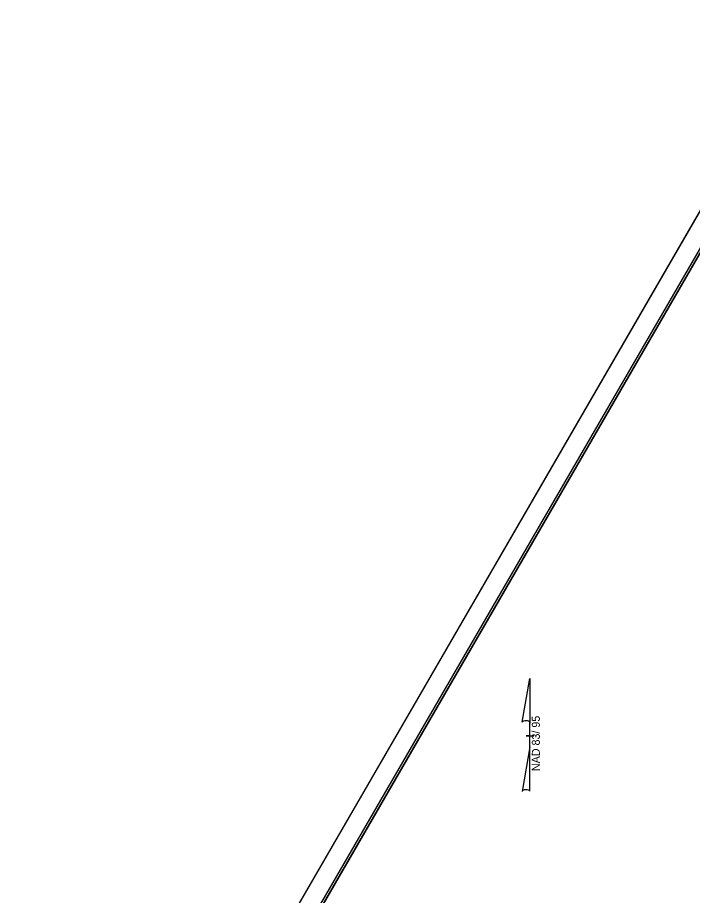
# Model space of a CAD drawing. Extents: x 1652765 to 1654556, y 596901 to 599124.
# Drawn here: x 1652765 to 1653481, y 597974 to 598906 of the extents above; entities that cross this region are included whole.
import ezdxf

# ---------------------------------------------------------------- set-up
doc = ezdxf.new("R2010")
doc.units = 0
for name, color, linetype in [('Prop Horizontal Alignment', 7, 'Continuous'), ('Prop Horizontal Alignment Tick Label', 7, 'Continuous'), ('Prop Horizontal Alignment Tick Small', 7, 'Continuous'), ('Prop North Arrow NAD83 for Plan Sheets CELL', 7, 'Continuous'), ('Sheet Cutting Line CELL', 7, 'Continuous'), ('Sheet Plan Layout CELL', 7, 'Continuous'), ('Sheet Plot Border Inside CELL', 7, 'Continuous')]:
    doc.layers.add(name, color=color, linetype=linetype)

msp = doc.modelspace()

# ---------------------------------------------------------------- linework, layer by layer
at = {"layer": 'Prop Horizontal Alignment'}
msp.add_lwpolyline([(1652892.65, 597625.47), (1653801.29, 597099.29), (1654314.56, 597985.64), (1654121.87, 598097.22), (1654310.18, 598422.41), (1653777.24, 598731.03), (1653682.4, 598567.24), (1653499.38, 598673.23)], close=True, dxfattribs=at)
at = {"layer": 'Prop Horizontal Alignment Tick Label'}
for points in [[(1653619.3, 598880.3), (1652867.59, 597582.21), (1653776.23, 597056.02), (1654527.93, 598354.1)], [(1653776.23, 597056.02), (1652867.6, 597582.17), (1653519.02, 598707.17), (1653648.89, 598631.98), (1653749.14, 598805.08), (1654527.93, 598354.1)]]:
    msp.add_lwpolyline(points, close=True, dxfattribs=at)
at = {"layer": 'Prop Horizontal Alignment Tick Small'}
msp.add_lwpolyline([(1653712.28, 596900.67), (1654555.93, 598357.53), (1653608.34, 598906.26), (1652764.7, 597449.4)], close=True, dxfattribs=at)
at = {"layer": 'Prop North Arrow NAD83 for Plan Sheets CELL'}
for p, q in [((1653300.62, 598158.12), (1653308.82, 598204.47)), ((1653308.87, 598204.47), (1653308.82, 598204.47)), ((1653308.87, 598204.47), (1653308.82, 598204.47)), ((1653308.87, 598204.47), (1653308.87, 598156.67)), ((1653308.87, 598131.87), (1653308.87, 598158.07)), ((1653308.87, 598156.67), (1653308.87, 598158.02)), ((1653304.87, 598143.47), (1653304.82, 598143.47)), ((1653308.42, 598143.47), (1653304.87, 598143.47)), ((1653304.92, 598143.47), (1653312.92, 598143.47)), ((1653308.87, 598131.87), (1653300.52, 598084.62)), ((1653308.92, 598084.82), (1653308.87, 598131.87))]:
    msp.add_line(p, q, dxfattribs=at)
for centre, start_param, end_param in [((1653304.76, 598157.63), 0.216388, 2.908219), ((1653304.76, 598084.46), 0.201328, 3.141593)]:
    msp.add_ellipse(centre, major_axis=(4.23, -0.03), ratio=0.461098, start_param=start_param, end_param=end_param, dxfattribs=at)
at = {"layer": 'Sheet Cutting Line CELL'}
msp.add_line((1653608.34, 598906.26), (1652764.7, 597449.4), dxfattribs=at)
at = {"layer": 'Sheet Plan Layout CELL'}
msp.add_lwpolyline([(1652867.6, 597582.17), (1653776.23, 597056.02), (1654527.92, 598354.08), (1653802.29, 598774.28), (1653682.4, 598567.24), (1653499.38, 598673.23)], close=True, dxfattribs=at)
at = {"layer": 'Sheet Plot Border Inside CELL'}
msp.add_lwpolyline([(1653701.49, 596921.94), (1654536.35, 598363.65), (1653623.4, 598892.34), (1652788.52, 597450.63)], close=True, dxfattribs=at)

# ---------------------------------------------------------------- texts
at = {"layer": 'Prop North Arrow NAD83 for Plan Sheets CELL'}
msp.add_text('NAD 83/ 95', height=8.5, rotation=90, dxfattribs=at).set_placement((1653319.39, 598106.23))

doc.saveas('drawing.dxf')
